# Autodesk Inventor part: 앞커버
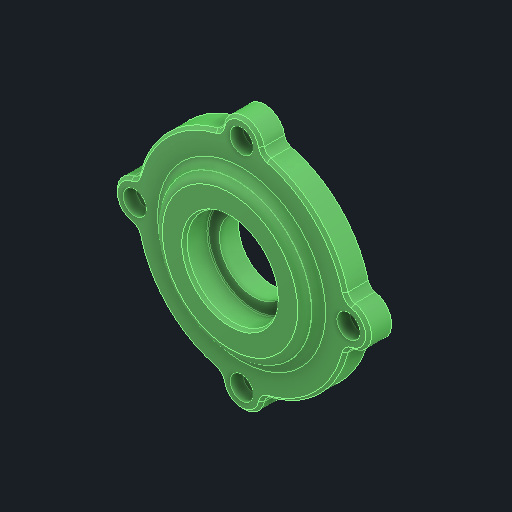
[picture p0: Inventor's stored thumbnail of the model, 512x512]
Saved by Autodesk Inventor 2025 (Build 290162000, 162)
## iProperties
Created: 2025-08
Part Number: 앞커버
Material: 알루미늄 6061
Document SubType Name: Modeling
Designer: infra17
Density: 2.71 g/cm^3
Appearance: 기본값
Company: 한국ATC센터
Author: jhkim
Sending System: Autodesk Inventor 2026
Preprocessor: ST-DEVELOPER v20.1
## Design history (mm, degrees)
feature "솔리드1"
node "솔리드2"
